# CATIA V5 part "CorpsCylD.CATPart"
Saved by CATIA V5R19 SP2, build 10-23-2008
Part number: CorpsCylC.2
Publications: "Dd", "DbCylD", "HcylD", "EcorpscylD", "DCyldExt"
Bounding box of the stored display mesh (mm): x -50 to 50, y 0 to 50, z 0 to 310
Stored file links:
  C:\Users\Vianney\Documents\Garantie\Cours\2A\IAO\IAO-proj-Catia\CorpsCylD.CATPart
  C:\Users\Vianney\Documents\Garantie\Cours\2A\IAO\IAO-proj-Catia\CylindreC.CATPart
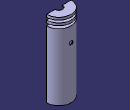
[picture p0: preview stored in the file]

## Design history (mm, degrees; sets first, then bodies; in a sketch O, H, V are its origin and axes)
Parameters
  EcorpscylD = 5 mm
  DbCylD = 30 mm
  Dd = 15 mm
  HcylD = 300 mm
  DCyldExt = 100 mm
Body1 (main body)
  Sketch1 on yz-plane, origin (0, 0, 0), H (0, 1, 0), V (0, 0, 1)
    line L1 (0, 0) -> (50, 0)
    line L2 (50, 0) -> (50, 270)
    line L3 (50, 270) -> (30, 270)
    line L4 (30, 270) -> (30, 280)
    line L5 (30, 280) -> (50, 280)
    point P5 (50, 280)
    line L6 (50, 280) -> (50, 290)
    line L7 (50, 290) -> (30, 290)
    point P7 (30, 290)
    line L8 (30, 290) -> (30, 300)
    line L9 (30, 300) -> (50, 300)
    point P9 (50, 300)
    line L10 (50, 300) -> (50, 310)
    line L11 (0, 0) -> (0, 5)
    line L12 (0, 5) -> (45, 5)
    line L13 (45, 5) -> (45, 265)
    line L14 (45, 265) -> (25, 265)
    line L15 (25, 265) -> (25, 305)
    line L16 (50, 310) -> (15, 310)
    line L17 (15, 310) -> (15, 305)
    line L18 (15, 305) -> (25, 305)
    length L2 = 270 {= HcylD -30mm}
    length L1 = 50 {= DCyldExt /2}
    distance L5 L1 = 280 {= HcylD -20mm}
    distance L7 L1 = 290 {= HcylD -10mm}
    distance L9 L1 = 300 {= HcylD}
    distance L15 L4 = 5 {= EcorpscylD}
    distance L17 V = 15 {= DbCylD /2}
    distance L1 L12 = 5 {= EcorpscylD}
    distance L13 L2 = 5 {= EcorpscylD}
    distance L14 L3 = 5 {= EcorpscylD}
    distance L18 L16 = 5 {= EcorpscylD}
    length L10 = 10
    distance L15 V = 25
    horizontal: L1 H, L3 H, L5 H, L7 H, L9 H, L12 H, L14 H, L16 H, L18 H
    vertical: L2 V, L4 V, L6 V, L8 V, L10 V, L11 V, L13 V, L15 V, L17 V
    coincidence: P5 L2, P7 L4, P9 L2
  Shaft1: profile Sketch1, axis Sketch1.V, angle 90, second angle 90
  Plane1: type Offset, RefPlane zx-plane, Offset 50 {= DCyldExt /2}
  Sketch2 on Plane1, origin (0, 50, 0), H (-1, 0, 0), V (0, 0, 1)
    circle A1 centre (0, 210) radius 7.5
    point P1 (0, 210)
    radius A1 = 7.5 {= Dd /2}
    distance P1 H = 210 {= HcylD -90mm}
    coincidence: P1 V
  Pocket1: profile Sketch2, direction (0, -1, 0), length 3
